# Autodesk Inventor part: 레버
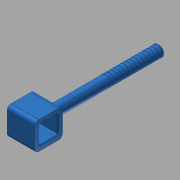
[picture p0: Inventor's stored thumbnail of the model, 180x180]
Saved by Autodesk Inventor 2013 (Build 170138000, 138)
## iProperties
Created: 2015-12
Part Number: 레버
Material: 스테인리스강
Document SubType Name: Modeling
Designer: mduedu
Density: 8.08 g/cm^3
Mass: 30.6794 g
Surface Area: 23.0487 cm^2
Volume: 3.79696 cm^3
Author: mduedu
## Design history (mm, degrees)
sketch "스케치1"
  geometry: C1 r 3 at (0, 0); 1 further point
  constraints: 1 centre point, 1 coincident
  dimensions: "d0" = 6 diameter of C1
extrude "돌출1" new body sketch "스케치1" distance "d1" = 60; taper "d2" = 0 deg
sketch "스케치5"
  geometry: L1 (-7.5, -7.5)-(7.5, -7.5); L2 (7.5, -7.5)-(7.5, 7.5); L3 (7.5, 7.5)-(-7.5, 7.5); L4 (-7.5, 7.5)-(-7.5, -7.5); L5 (-7.5, -7.5)-(7.5, 7.5); L6 (7.5, -7.5)-(-7.5, 7.5); C1 r 3 at (0, 0) reference
  constraints: 12 end point, 2 midpoint, 2 parallel, 2 perpendicular, 1 horizontal
  dimensions: "d24" = 15 distance of L2.end L3.end
extrude "돌출2" join sketch "스케치5" distance "d26" = 15; taper "d27" = 0 deg
chamfer "모따기1" distance "d7" = 0.5; stored, may be unused: second distance "d8" = 2, angle "d9" = 45 deg
fillet "모깎기2" dims "d11" = 1
sketch "스케치4"
  geometry: L1 (-60, -2.5)-(-60, 2.5) reference; L2 (-60, 0)-(0, 0); L3 (-1, 3)-(-59.5, 3) reference; L4 (-59, 3)-(-58.9, 3); L5 (-58.9, 3)-(-58.9, 2.9); L6 (-58.9, 2.9)-(-59, 2.9); L7 (-59, 2.9)-(-59, 3)
  constraints: 10 end point, 2 parallel, 2 perpendicular, 1 horizontal, 1 midpoint, 1 point on line
  dimensions: "d17" = 1 distance between parallel lines of L7 L1; "d18" = 0.1 distance of L5.end L6.end; "d19" = 0.1 distance of L4.end L5.end
revolve "회전3" sketch "스케치4" stored, may be unused: angle "d20" = 90 deg
sketch "스케치6"
  geometry: L1 (0, 0)-(15, 0) reference; L2 (15, 15)-(15, 0) reference; L3 (0, 15)-(15, 15) reference; L4 (7.5, 15)-(7.5, 0); L5 (0, 7.5)-(15, 7.5); L6 (2.5, 2.5)-(12.5, 2.5); L7 (12.5, 2.5)-(12.5, 12.5); L8 (12.5, 12.5)-(2.5, 12.5); L9 (2.5, 12.5)-(2.5, 2.5); L10 (2.5, 2.5)-(12.5, 12.5); L11 (12.5, 2.5)-(2.5, 12.5); 1 further point
  constraints: 16 end point, 6 midpoint, 2 parallel, 2 perpendicular, 1 horizontal
  dimensions: "d29" = 10 distance of L7.end L8.end; "d31" = 2.5 distance between parallel lines of L8 L3 (derived)
extrude "돌출3" cut sketch "스케치6" stored distance "d32" = 15; taper "d33" = 0 deg
fillet "모깎기3" dims "d34" = 2, "d35" = 1
chamfer "모따기2" distance "d36" = 0.5; stored, may be unused: second distance "d37" = 2, angle "d38" = 45 deg
node "솔리드1"
pattern_linear "직사각형 패턴1" dims "d23" = 2
